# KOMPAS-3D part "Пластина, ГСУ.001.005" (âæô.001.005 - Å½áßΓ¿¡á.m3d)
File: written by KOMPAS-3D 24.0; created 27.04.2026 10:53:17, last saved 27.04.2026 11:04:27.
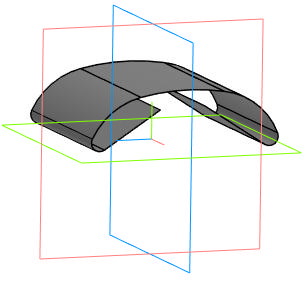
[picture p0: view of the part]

Document properties: Автор: User7; Полное имя файла: C:\Users\User7\Desktop\олимп\ГСУ.001.005 - Пластина.m3d

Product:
- Part/product: Пластина  | designation ГСУ.001.005
    Масса: 0.002726

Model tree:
1. Эскиз:1
2. Элемент выдавливания:1
     Толщина стенки 1 = 0.1; Расстояние 1 = 38

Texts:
  ГСУ.001.005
